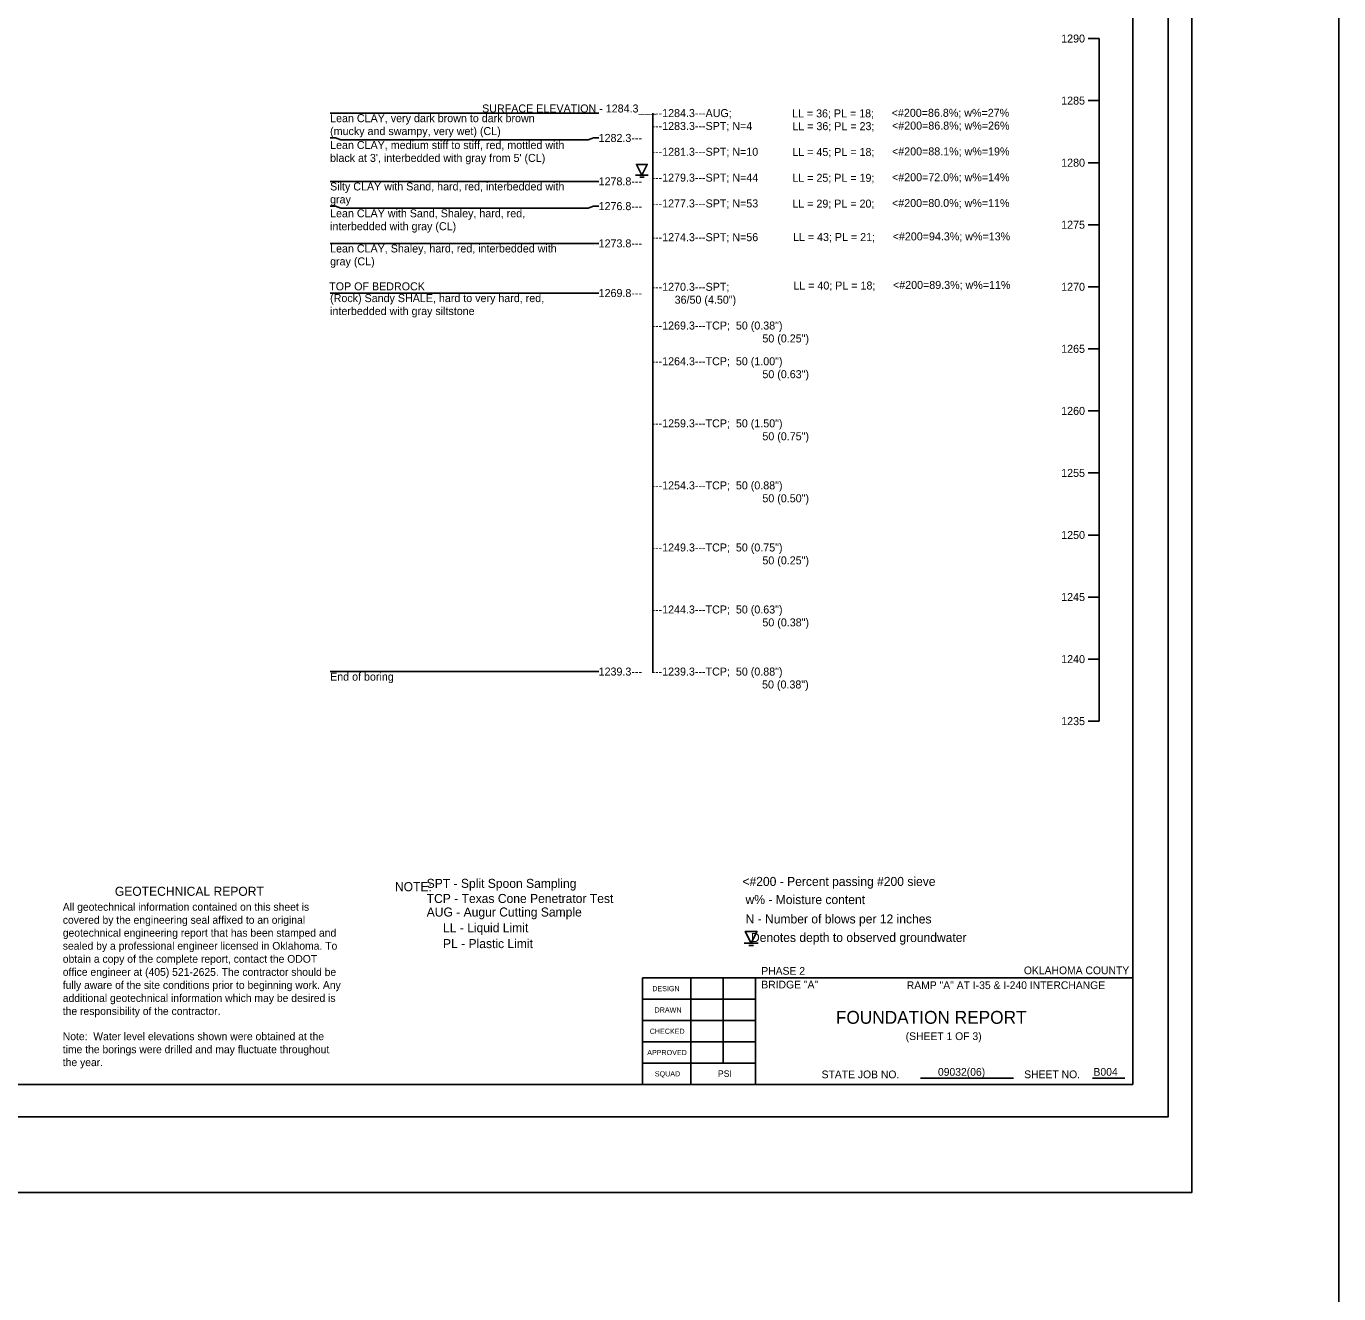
# Model space of a CAD drawing. Extents: x 2150161.5 to 2150203.1, y 143779.5 to 143868.5.
# Drawn here: x 2150182.73 to 2150203.07, y 143834.58 to 143854.22 of the extents above; entities that cross this region are included whole.
import ezdxf

# ---------------------------------------------------------------- set-up
doc = ezdxf.new("R2010")
doc.units = 0
for name, color, linetype in [('Default', 7, 'Continuous'), ('S', 7, 'Continuous'), ('SHT_Plot_Shape_Full', 7, 'Continuous'), ('SHT_Plot_Shape_Half', 7, 'Continuous'), ('SHT_Sheet_Border', 7, 'Continuous'), ('SHT_Standard_Sheet_Lines', 7, 'Continuous'), ('SHT_Standard_Sheet_Txt', 7, 'Continuous'), ('T', 7, 'Continuous'), ('T-Title', 7, 'Continuous'), ('Text', 7, 'Continuous')]:
    doc.layers.add(name, color=color, linetype=linetype)

# ---------------------------------------------------------------- blocks, each defined once
blk = doc.blocks.new('DGRFC_WTLEV1')
at = {"layer": 'Default'}
for points in [[(-0.0127, 0), (0.0127, 0)], [(0, 0), (0.0106, 0.0212), (-0.0106, 0.0212), (0, 0)], [(-0.0042, -0.0042), (0.0042, -0.0042)]]:
    blk.add_lwpolyline(points, dxfattribs=at)

msp = doc.modelspace()

# ---------------------------------------------------------------- linework, layer by layer
at = {"layer": 'Default'}
msp.add_line((2150199.355, 143843.45), (2150199.355, 143854.027), dxfattribs=at)
for points in [[(2150199.355, 143854.027), (2150199.188, 143854.027)], [(2150199.355, 143853.065), (2150199.188, 143853.065)], [(2150187.438, 143852.872), (2150191.604, 143852.872)], [(2150192.438, 143852.869), (2150192.438, 143844.209)], [(2150187.438, 143852.487), (2150187.521, 143852.487), (2150187.604, 143852.455), (2150191.438, 143852.455), (2150191.521, 143852.487), (2150191.604, 143852.487)], [(2150199.355, 143852.103), (2150199.188, 143852.103)], [(2150187.438, 143851.814), (2150191.604, 143851.814)], [(2150187.438, 143851.43), (2150187.521, 143851.43), (2150187.604, 143851.397), (2150191.438, 143851.397), (2150191.521, 143851.43), (2150191.604, 143851.43)], [(2150199.355, 143851.142), (2150199.188, 143851.142)], [(2150187.438, 143850.853), (2150191.604, 143850.853)], [(2150199.355, 143850.18), (2150199.188, 143850.18)], [(2150187.438, 143850.083), (2150191.604, 143850.083)], [(2150199.355, 143849.219), (2150199.188, 143849.219)], [(2150199.355, 143848.257), (2150199.188, 143848.257)], [(2150199.355, 143847.296), (2150199.188, 143847.296)], [(2150199.355, 143846.334), (2150199.188, 143846.334)], [(2150199.355, 143845.373), (2150199.188, 143845.373)], [(2150199.355, 143845.373), (2150199.188, 143845.373)], [(2150199.355, 143844.411), (2150199.188, 143844.411)], [(2150199.355, 143844.411), (2150199.188, 143844.411)], [(2150187.438, 143844.218), (2150191.604, 143844.218)], [(2150199.355, 143843.45), (2150199.188, 143843.45)], [(2150199.355, 143843.45), (2150199.188, 143843.45)]]:
    msp.add_lwpolyline(points, dxfattribs=at)
at = {"layer": 'S'}
msp.add_lwpolyline([(2150161.53, 143868.477), (2150203.071, 143868.477), (2150203.071, 143779.536), (2150161.53, 143779.536)], close=True, dxfattribs=at)
at = {"layer": 'SHT_Plot_Shape_Full'}
msp.add_lwpolyline([(2150164.792, 143860.145), (2150200.792, 143860.145), (2150200.792, 143836.145), (2150164.792, 143836.145)], close=True, dxfattribs=at)
at = {"layer": 'SHT_Plot_Shape_Half'}
msp.add_lwpolyline([(2150166.429, 143859.32), (2150200.429, 143859.32), (2150200.429, 143837.32), (2150166.429, 143837.32)], close=True, dxfattribs=at)
at = {"layer": 'SHT_Sheet_Border'}
for p, q in [((2150192.279, 143837.82), (2150192.279, 143839.47)), ((2150192.279, 143839.47), (2150199.879, 143839.47)), ((2150194.029, 143837.82), (2150194.029, 143839.471))]:
    msp.add_line(p, q, dxfattribs=at)
msp.add_lwpolyline([(2150199.879, 143837.82), (2150168.379, 143837.82), (2150168.379, 143858.82), (2150199.879, 143858.82)], close=True, dxfattribs=at)
at = {"layer": 'SHT_Standard_Sheet_Lines'}
for p, q in [((2150193.029, 143837.82), (2150193.029, 143839.471)), ((2150193.529, 143838.15), (2150193.529, 143839.471)), ((2150196.59, 143837.916), (2150198.03, 143837.917)), ((2150199.255, 143837.916), (2150199.757, 143837.917))]:
    msp.add_line(p, q, dxfattribs=at)
for points in [[(2150194.029, 143839.14), (2150192.279, 143839.14)], [(2150194.029, 143838.81), (2150192.279, 143838.81)], [(2150194.029, 143838.48), (2150192.279, 143838.48)], [(2150194.029, 143838.15), (2150192.279, 143838.15)]]:
    msp.add_lwpolyline(points, dxfattribs=at)

# ---------------------------------------------------------------- block references
at = {"layer": 'Default'}
for p, xscale, yscale in [((2150192.27, 143851.91), 7.873999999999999, 7.873999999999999), ((2150193.962, 143840.011), 8.503919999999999, 8.503919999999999)]:
    msp.add_blockref('DGRFC_WTLEV1', p, dxfattribs=dict(at, xscale=xscale, yscale=yscale))

# ---------------------------------------------------------------- texts
for s, p in [('1290', (2150198.769, 143853.965)), ('1285', (2150198.769, 143853.003)), ('1280', (2150198.769, 143852.041)), ('1275', (2150198.769, 143851.08)), ('1270', (2150198.769, 143850.118)), ('1265', (2150198.769, 143849.157)), ('1260', (2150198.769, 143848.195)), ('1255', (2150198.769, 143847.234)), ('1250', (2150198.769, 143846.272)), ('1245', (2150198.769, 143845.311)), ('1240', (2150198.769, 143844.349)), ('1235', (2150198.769, 143843.388))]:
    msp.add_text(s, height=0.124, rotation=0.0001, dxfattribs=at).set_placement(p)
for s, p in [('Lean CLAY, very dark brown to dark brown', (2150187.438, 143852.731)), ('SURFACE ELEVATION - 1284.3___', (2150189.794, 143852.881)), ('---1284.3---AUG;', (2150192.419, 143852.81)), ('LL = 36; PL = 18;', (2150194.597, 143852.805)), ('<#200=86.8%; w%=27%', (2150196.142, 143852.814)), ('(mucky and swampy, very wet) (CL)', (2150187.438, 143852.531)), ('---1283.3---SPT; N=4', (2150192.419, 143852.61)), ('LL = 36; PL = 23;', (2150194.602, 143852.607)), ('<#200=86.8%; w%=26%', (2150196.147, 143852.616)), ('Lean CLAY, medium stiff to stiff, red, mottled with', (2150187.438, 143852.315)), ('1282.3---', (2150191.6, 143852.425)), ("black at 3', interbedded with gray from 5' (CL)", (2150187.438, 143852.115)), ('---1281.3---SPT; N=10', (2150192.419, 143852.21)), ('LL = 45; PL = 18;', (2150194.602, 143852.207)), ('<#200=88.1%; w%=19%', (2150196.147, 143852.216)), ('Silty CLAY with Sand, hard, red, interbedded with', (2150187.438, 143851.673)), ('1278.8---', (2150191.6, 143851.752)), ('---1279.3---SPT; N=44', (2150192.419, 143851.81)), ('LL = 25; PL = 19;', (2150194.602, 143851.807)), ('<#200=72.0%; w%=14%', (2150196.147, 143851.816)), ('gray', (2150187.438, 143851.473)), ('1276.8---', (2150191.6, 143851.368)), ('---1277.3---SPT; N=53', (2150192.419, 143851.41)), ('LL = 29; PL = 20;', (2150194.602, 143851.407)), ('<#200=80.0%; w%=11%', (2150196.147, 143851.416)), ('Lean CLAY with Sand, Shaley, hard, red,', (2150187.438, 143851.257)), ('interbedded with gray (CL)', (2150187.438, 143851.057)), ('---1274.3---SPT; N=56', (2150192.419, 143850.887)), ('LL = 43; PL = 21;', (2150194.612, 143850.889)), ('<#200=94.3%; w%=13%', (2150196.157, 143850.899)), ('Lean CLAY, Shaley, hard, red, interbedded with', (2150187.438, 143850.712)), ('1273.8---', (2150191.6, 143850.791)), ('gray (CL)', (2150187.438, 143850.512)), ('TOP OF BEDROCK', (2150187.424, 143850.125)), ('---1270.3---SPT;', (2150192.419, 143850.118)), ('LL = 40; PL = 18;', (2150194.617, 143850.138)), ('<#200=89.3%; w%=11%', (2150196.162, 143850.147)), ('(Rock) Sandy SHALE, hard to very hard, red,', (2150187.438, 143849.943)), ('1269.8---', (2150191.6, 143850.021)), ('36/50 (4.50")', (2150192.778, 143849.918)), ('interbedded with gray siltstone', (2150187.438, 143849.743)), ('---1269.3---TCP;  50 (0.38")', (2150192.419, 143849.518)), ('50 (0.25")', (2150194.138, 143849.318)), ('---1264.3---TCP;  50 (1.00")', (2150192.419, 143848.964)), ('50 (0.63")', (2150194.138, 143848.764)), ('---1259.3---TCP;  50 (1.50")', (2150192.419, 143848.002)), ('50 (0.75")', (2150194.138, 143847.802)), ('---1254.3---TCP;  50 (0.88")', (2150192.419, 143847.041)), ('50 (0.50")', (2150194.138, 143846.841)), ('---1249.3---TCP;  50 (0.75")', (2150192.419, 143846.079)), ('50 (0.25")', (2150194.138, 143845.879)), ('---1244.3---TCP;  50 (0.63")', (2150192.419, 143845.118)), ('50 (0.38")', (2150194.138, 143844.918)), ('1239.3---', (2150191.6, 143844.156)), ('---1239.3---TCP;  50 (0.88")', (2150192.419, 143844.156)), ('End of boring', (2150187.438, 143844.077)), ('50 (0.38")', (2150194.133, 143843.956))]:
    msp.add_text(s, height=0.124, dxfattribs=at).set_placement(p)
at = {"layer": 'SHT_Standard_Sheet_Txt'}
for s, height, p in [('DESIGN', 0.08, (2150192.431, 143839.265)), ('DRAWN', 0.08, (2150192.467, 143838.935)), ('CHECKED', 0.08, (2150192.392, 143838.605)), ('APPROVED', 0.08, (2150192.353, 143838.275)), ('SQUAD', 0.08, (2150192.471, 143837.945)), ('STATE JOB NO.', 0.12, (2150195.056, 143837.916)), ('SHEET NO. ', 0.12, (2150198.196, 143837.917))]:
    msp.add_text(s, height=height, dxfattribs=at).set_placement(p)
at = {"layer": 'T'}
for s, height, p in [('PHASE 2', 0.12, (2150194.121, 143839.52)), ('OKLAHOMA COUNTY', 0.12, (2150198.191, 143839.528)), ('BRIDGE "A"', 0.12, (2150194.121, 143839.308)), ('RAMP "A" AT I-35 & I-240 INTERCHANGE', 0.12, (2150196.376, 143839.298)), ('(SHEET 1 OF 3)', 0.12, (2150196.359, 143838.508)), ('PSI', 0.1, (2150193.449, 143837.938)), ('09032(06)', 0.12, (2150196.859, 143837.955)), ('B004', 0.12, (2150199.27, 143837.955))]:
    msp.add_text(s, height=height, dxfattribs=at).set_placement(p)
at = {"layer": 'T-Title'}
msp.add_text('FOUNDATION REPORT', height=0.2, dxfattribs=at).set_placement((2150195.276, 143838.76))
at = {"layer": 'Text'}
for s, height, p in [(' <#200 - Percent passing #200 sieve', 0.14, (2150193.777, 143840.896)), ('GEOTECHNICAL REPORT', 0.14, (2150184.102, 143840.743)), ('NOTE:', 0.14, (2150188.443, 143840.815)), ('    SPT - Split Spoon Sampling', 0.14, (2150188.727, 143840.866)), ('All geotechnical information contained on this sheet is ', 0.12, (2150183.295, 143840.512)), ('    TCP - Texas Cone Penetrator Test', 0.14, (2150188.727, 143840.632)), ('w% - Moisture content', 0.14, (2150193.877, 143840.615)), ('covered by the engineering seal affixed to an original ', 0.12, (2150183.295, 143840.31)), ('    AUG - Augur Cutting Sample', 0.14, (2150188.727, 143840.422)), ('N - Number of blows per 12 inches', 0.14, (2150193.877, 143840.315)), ('geotechnical engineering report that has been stamped and ', 0.12, (2150183.295, 143840.11)), (' LL - Liquid Limit', 0.14, (2150189.136, 143840.179)), ('sealed by a professional engineer licensed in Oklahoma. To ', 0.12, (2150183.295, 143839.908)), (' PL - Plastic Limit', 0.14, (2150189.136, 143839.933)), ('    Denotes depth to observed groundwater', 0.14, (2150193.753, 143840.028)), ('obtain a copy of the complete report, contact the ODOT ', 0.12, (2150183.295, 143839.706)), ('office engineer at (405) 521-2625. The contractor should be ', 0.12, (2150183.295, 143839.503)), ('fully aware of the site conditions prior to beginning work. Any ', 0.12, (2150183.295, 143839.301)), ('additional geotechnical information which may be desired is ', 0.12, (2150183.295, 143839.099)), ('the responsibility of the contractor.', 0.12, (2150183.295, 143838.897)), ('Note:  Water level elevations shown were obtained at the ', 0.12, (2150183.295, 143838.506)), ('time the borings were drilled and may fluctuate throughout ', 0.12, (2150183.295, 143838.304)), ('the year.', 0.12, (2150183.295, 143838.104))]:
    msp.add_text(s, height=height, dxfattribs=at).set_placement(p)

doc.saveas('drawing.dxf')
